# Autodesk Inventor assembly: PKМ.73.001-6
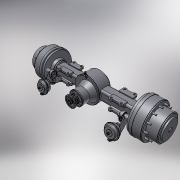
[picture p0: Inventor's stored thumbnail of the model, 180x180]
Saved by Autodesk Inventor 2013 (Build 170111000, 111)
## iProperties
Created: 2005-03
Part Number: PKМ.73.001-6
Document SubType Name: Assembly
Designer: salex
Manufacturer: Standard
Standards Organization: Custom
Author: salex
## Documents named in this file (21)
- D:\FrontLoaderVault\Data\Assy, Chassis, Front\ODM.73.001-6.iam
- D:\FrontLoaderVault\Data\Assy, Chassis, Front\Beam Bridge.ipt
- D:\FrontLoaderVault\Data\Assy, Chassis, Front\Hub D.ipt
- D:\FrontLoaderVault\Data\Assy, Chassis, Front\PK46.42.00.001.ipt
- D:\FrontLoaderVault\Data\Assy, Chassis, Front\PK46.42.00.020.iam
- D:\FrontLoaderVault\Data\Assy, Chassis, Front\Brake Lever B.ipt
- D:\FrontLoaderVault\Data\Assy, Chassis, Front\Pneumatic Chamber B.ipt
- D:\FrontLoaderVault\Data\Assy, Chassis, Front\The Rod Pneumatic Chamber.ipt
- D:\FrontLoaderVault\Data\Assy, Chassis, Front\Lead Flange A.ipt
- D:\FrontLoaderVault\Data\Assy, Chassis, Front\Bracket pneumatic chamber 1.ipt
- D:\FrontLoaderVault\Data\Assy, Chassis, Front\Bracket pneumatic chamber 1_MIR.ipt
- D:\FrontLoaderVault\Data\Assy, Chassis, Front\Fork E.ipt
- Beam Bridge.ipt
- Hub D.ipt
- Bracket pneumatic chamber 1.ipt
- Brake Lever B.ipt
- Pneumatic Chamber B.ipt
- The Rod Pneumatic Chamber.ipt
- Lead Flange A.ipt
- Bracket pneumatic chamber 1_MIR.ipt
- Fork E.ipt
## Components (16 placed, 11 different names)
1. Beam Bridge:1 — Insert:1, Insert:2, Flush:1, Flush:2, Mate:18, Flush:6, Mate:19, Flush:7, Flush:8, Angle:5, Mate:38, Mate:39, Angle:10, Mate:40, Mate:43
2. Hub D:1 — Insert:2, Flush:2, Mate:1, Angle:4, Angle:8, Mate:42
3. Hub D:2 — Insert:1, Flush:1
4. Bracket pneumatic chamber 1:1 — Mate:12, Insert:3, Mate:14, Mate:9, Flush:7, Flush:9, Mate:25, Angle:5, Mate:35, Mate:42, Mate:43
5. Brake Lever B:1 — Mate:12, Mate:9, Mate:36
6. Brake Lever B:2 — Mate:27, Mate:28, Insert:8, Mate:41
7. Pneumatic Chamber B:1 — Insert:3, Mate:14, Angle:6, Insert:9
8. Pneumatic Chamber B:2 — Insert:7, Mate:26, Insert:10
9. The Rod Pneumatic Chamber:1 — Mate:35, Angle:6, Mate:36, Angle:7
10. The Rod Pneumatic Chamber:2 — Insert:8, Angle:7, Mate:37, Insert:11
11. Lead Flange A:1 — Mate:18, Flush:6, Mate:19
12. Bracket pneumatic chamber 1_MIR:1 — Flush:8, Flush:9, Mate:25, Insert:7, Mate:26, Mate:27, Mate:28, Mate:37
13. PK46.42.00.001:1 — Insert:9, Angle:8, Angle:9
14. PK46.42.00.001:2 — Insert:10, Angle:9
15. PK46.42.00.020:1 [sub-assembly] — Mate:38, Mate:39, Angle:10, Mate:40
16. ПК46.51.11.003:1 — Insert:11, Mate:41
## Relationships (40: Mate 19, Insert 8, Angle 7, Flush 6)
- Insert:1: Beam Bridge:1 ↔ Hub D:2
- Insert:2: Beam Bridge:1 ↔ Hub D:1
- Flush:1: Beam Bridge:1 ↔ Hub D:2
- Flush:2: Beam Bridge:1 ↔ Hub D:1
- Mate:1: Hub D:1
- Mate:12: Bracket pneumatic chamber 1:1 ↔ Brake Lever B:1
- Insert:3: Bracket pneumatic chamber 1:1 ↔ Pneumatic Chamber B:1
- Mate:14: Bracket pneumatic chamber 1:1 ↔ Pneumatic Chamber B:1
- Mate:18: Beam Bridge:1 ↔ Lead Flange A:1
- Flush:6: Beam Bridge:1 ↔ Lead Flange A:1
- Mate:19: Beam Bridge:1 ↔ Lead Flange A:1
- Mate:9: Bracket pneumatic chamber 1:1 ↔ Brake Lever B:1
- Flush:7: Beam Bridge:1 ↔ Bracket pneumatic chamber 1:1
- Flush:8: Beam Bridge:1 ↔ Bracket pneumatic chamber 1_MIR:1
- Flush:9: Bracket pneumatic chamber 1:1 ↔ Bracket pneumatic chamber 1_MIR:1
- Mate:25: Bracket pneumatic chamber 1:1 ↔ Bracket pneumatic chamber 1_MIR:1
- Insert:7: Pneumatic Chamber B:2 ↔ Bracket pneumatic chamber 1_MIR:1
- Mate:26: Pneumatic Chamber B:2 ↔ Bracket pneumatic chamber 1_MIR:1
- Mate:27: Brake Lever B:2 ↔ Bracket pneumatic chamber 1_MIR:1
- Mate:28: Brake Lever B:2 ↔ Bracket pneumatic chamber 1_MIR:1
- Angle:4: Hub D:1
- Angle:5: Beam Bridge:1 ↔ Bracket pneumatic chamber 1:1
- Mate:35: Bracket pneumatic chamber 1:1 ↔ The Rod Pneumatic Chamber:1
- Angle:6: Pneumatic Chamber B:1 ↔ The Rod Pneumatic Chamber:1
- Mate:36: Brake Lever B:1 ↔ The Rod Pneumatic Chamber:1
- Insert:8: Brake Lever B:2 ↔ The Rod Pneumatic Chamber:2
- Angle:7: The Rod Pneumatic Chamber:1 ↔ The Rod Pneumatic Chamber:2
- Mate:37: The Rod Pneumatic Chamber:2 ↔ Bracket pneumatic chamber 1_MIR:1
- Insert:9: Pneumatic Chamber B:1 ↔ PK46.42.00.001:1
- Insert:10: Pneumatic Chamber B:2 ↔ PK46.42.00.001:2
- Angle:8: Hub D:1 ↔ PK46.42.00.001:1
- Angle:9: PK46.42.00.001:1 ↔ PK46.42.00.001:2
- Mate:38: Beam Bridge:1 ↔ PK46.42.00.020:1
- Mate:39: Beam Bridge:1 ↔ PK46.42.00.020:1
- Angle:10: Beam Bridge:1 ↔ PK46.42.00.020:1
- Mate:40: Beam Bridge:1 ↔ PK46.42.00.020:1
- Insert:11: The Rod Pneumatic Chamber:2 ↔ ПК46.51.11.003:1
- Mate:41: Brake Lever B:2 ↔ ПК46.51.11.003:1
- Mate:42: Hub D:1 ↔ Bracket pneumatic chamber 1:1
- Mate:43: Beam Bridge:1 ↔ Bracket pneumatic chamber 1:1
